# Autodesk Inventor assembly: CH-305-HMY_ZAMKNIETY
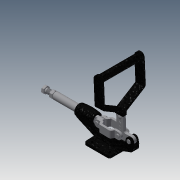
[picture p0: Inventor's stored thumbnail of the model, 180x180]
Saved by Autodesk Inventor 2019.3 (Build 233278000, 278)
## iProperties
Company: Î¢ÈíÖÐ¹ú
Created: 2015-08
Part Number: CH-305-HMY_ZAMKNIETY
Material: Ogólny
Description: STEP AP203
Document SubType Name: Assembly
Designer: CADENGINEERING4
Sending System: SolidWorks 2012
Preprocessor: SwSTEP 2.0
Title: CH-305-HMY.STEP
Author: Î¢ÈíÓÃ»§
Revision Number: ÈÎºÎ
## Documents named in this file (13)
- D:\Vault_2016\Projekty\STRONA\Push-pull clamp\CH-305-HMY\CH-305-HMY_ZAMKNIETY.iam
- D:\Vault_2016\Projekty\STRONA\Push-pull clamp\CH-305-HMY\CH-304-HM-01 BASE.ipt
- D:\Vault_2016\Projekty\STRONA\Push-pull clamp\CH-305-HMY\CH-304-HM-02 CREST STALK.ipt
- D:\Vault_2016\Projekty\STRONA\Push-pull clamp\CH-305-HMY\CH-304-HM-07.ipt
- D:\Vault_2016\Projekty\STRONA\Push-pull clamp\CH-305-HMY\CH-304-HM-04 CONNECTING-PLATE.ipt
- D:\Vault_2016\Projekty\STRONA\Push-pull clamp\CH-305-HMY\CH-304-HM-06.ipt
- D:\Vault_2016\Projekty\STRONA\Push-pull clamp\CH-305-HMY\304-05.ipt
- D:\Vault_2016\Projekty\STRONA\Push-pull clamp\CH-305-HMY\5-16 LOCK NUT.ipt
- D:\Vault_2016\Projekty\STRONA\Push-pull clamp\CH-305-HMY\M12 Nut.ipt
- D:\Vault_2016\Projekty\STRONA\Push-pull clamp\CH-305-HMY\CH-SA-125017 SPINDLE SUPPLIED.ipt
- D:\Vault_2016\Projekty\STRONA\Push-pull clamp\CH-305-HMY\CH-305-HMY HANDLE.ipt
- D:\Vault_2016\Projekty\STRONA\Push-pull clamp\CH-305-HMY\CH-305-HMY-06.ipt
- D:\Vault_2016\Projekty\STRONA\Push-pull clamp\CH-305-HMY\CH-305-HMY-087.ipt
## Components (16 placed, 16 different names)
1. CH-304-HM-01 BASE_1
2. CH-304-HM-02 CREST STALK_2
3. CH-304-HM-07_3
4. CH-304-HM-07_4
5. CH-304-HM-04 CONNECTING-PLATE_5
6. CH-304-HM-04 CONNECTING-PLATE_6
7. CH-304-HM-06_7
8. 304-05_8
9. CH-304-HM-06_9
10. 5-16 LOCK NUT_10
11. 5-16 LOCK NUT_11
12. M12 Nut_12
13. CH-SA-125017 SPINDLE SUPPLIED_13
14. CH-305-HMY HANDLE_14
15. CH-305-HMY-06_15
16. CH-305-HMY-087_16
